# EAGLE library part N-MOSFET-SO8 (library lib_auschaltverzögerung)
N-Channel MOSFET Example: FDS7760A; N-Channel Logic Level PowerTrench® MOSFET FDS2572; N-Channel UltraFET® Trench MOSFET Source: www.fairchildsemi.com
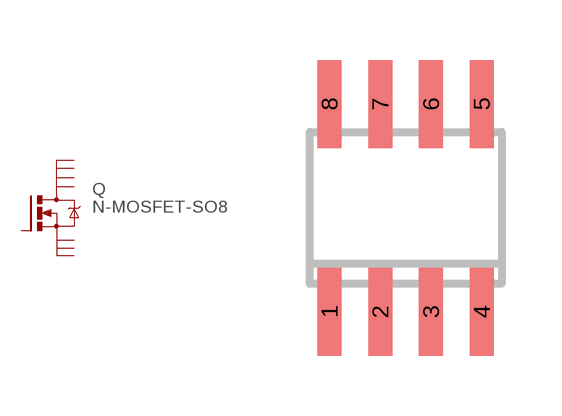
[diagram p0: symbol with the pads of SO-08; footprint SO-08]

Designator prefix Q

## N-MOSFET-SO8S  [SO-08]
1  S  pas
2  S  pas
3  S  pas
4  G  pas
5  D  pas
6  D  pas
7  D  pas
8  D  pas

## Footprint SO-08 (pad centres in mm)
Small Outline Narrow Plastic Gull Wing 150-mil body, package type SN
smd 0.6 x 2.2: 1 -1.905,-2.6; 2 -0.635,-2.6; 3 0.635,-2.6; 4 1.905,-2.6; 5 1.905,2.6; 6 0.635,2.6; 7 -0.635,2.6; 8 -1.905,2.6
